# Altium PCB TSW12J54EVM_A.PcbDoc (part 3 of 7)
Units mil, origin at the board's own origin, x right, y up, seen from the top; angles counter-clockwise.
Board outline 6301 x 2680 mil, 10 copper layers (Top Layer - L1, Gnd-Plane - L2, Signals - L3, Gnd-Plane - L4, Pwr Plane - L5, Signals - L6, Gnd-Plane - L7, Signals - L8, Gnd-Plane - L9, Bottom Layer - L10), stack 57.8 mil thick; 650 components, 374 nets, 2074 pads, 1402 vias.
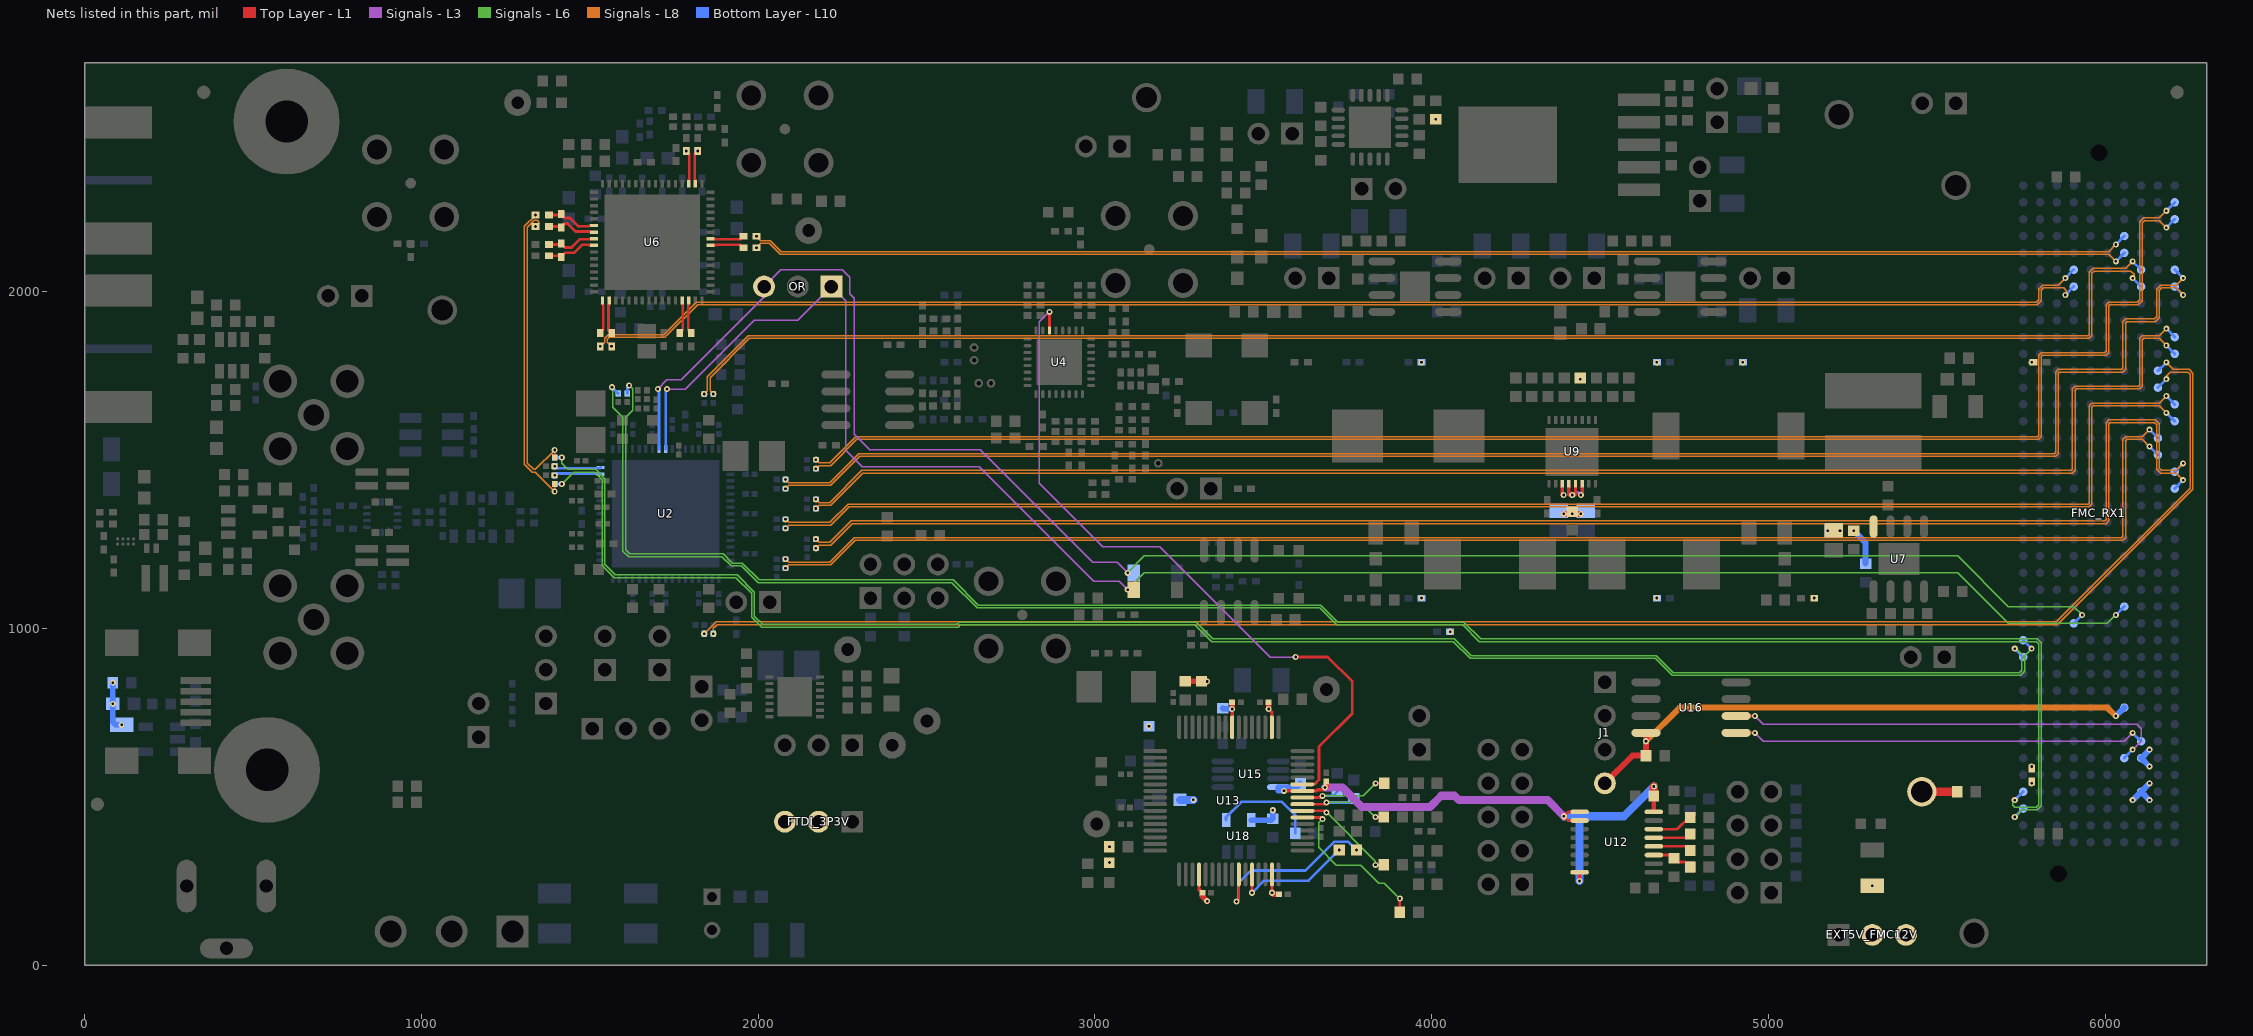
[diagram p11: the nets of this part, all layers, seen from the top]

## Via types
v1: diameter 18, hole 8, Top Layer - L1 to Bottom Layer - L10, tented both sides, 1120 vias
v2: diameter 19.68, hole 7.87, Top Layer - L1 to Bottom Layer - L10, 99 vias
v3: diameter 18, hole 8, Top Layer - L1 to Bottom Layer - L10, tented bottom, 42 vias
v4: diameter 18, hole 8, Top Layer - L1 to Bottom Layer - L10, tented top, 36 vias
v5: diameter 25, hole 10, Top Layer - L1 to Bottom Layer - L10, tented both sides, 32 vias
v6: diameter 21.46, hole 10, Top Layer - L1 to Bottom Layer - L10, tented both sides, 26 vias
v7: diameter 18, hole 8.01, Top Layer - L1 to Bottom Layer - L10, tented both sides, 16 vias
v8: diameter 18, hole 8.01, Top Layer - L1 to Bottom Layer - L10, tented bottom, 16 vias
v9: diameter 25.98, hole 12.99, Top Layer - L1 to Bottom Layer - L10, tented top, 8 vias
v10: diameter 19.68, hole 7.87, Top Layer - L1 to Bottom Layer - L10, tented top, 5 vias
v11: diameter 126, hole 106, Top Layer - L1 to Bottom Layer - L10, tented top, 2 vias

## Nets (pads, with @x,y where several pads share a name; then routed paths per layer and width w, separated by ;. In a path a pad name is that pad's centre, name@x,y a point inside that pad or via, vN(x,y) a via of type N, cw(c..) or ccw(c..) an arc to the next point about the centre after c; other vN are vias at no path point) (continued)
3P3V_FTDI: C118.1 C119.1 C129.1 C131.1 C132.1 C205.1 C213.1 C214.1 FTDI_3P3V.2 L24.1 L25.1 R66.2 R105.2 R106.2 R107.2 U12.1 U12.2 U12.8 U12.16 U13.20 U13.31 U13.42 U13.50 U13.56 U15.8 U18.5 USB_PWR.1 | length 2260.4
  Top Layer - L1 w8: U12.2@4438.76,429.5 4404.79,429.5 v1(4392,442.3) 4404.8,455.1 U12.1@4438.76,455.1
  Top Layer - L1 w10: U13.20@3308.89,269.5 3308.89,224.87 C118.1@3318.73,215.03 ; U13.56@3407.31,706.5 v1(3407.31,760.97) ; v1(3515.58,760.97) 3525.42,751.13 U13.50@3525.42,706.5 ; v1(3525.43,215.03) U13.31@3525.42,269.5 ; v1(3561.51,517.53) U13.42@3615.98,517.53 3658.83,517.53 3662.14,520.84 3676.47,520.84 v1(3683,527.37)
  Top Layer - L1 w13: v1(4438.76,250) U12.8@4438.76,275.96 ; U12.16@4659.24,455.1 C129.1@4659.24,502.06
  Top Layer - L1 w16: v1(3683,527.37) 3686.44,530.82 C131.1@3686.44,545.43
  Top Layer - L1 w16.5: R107.2@3268.2,842.56 v1(3333,842.56) ; C118.1@3318.73,215.03 3318.73,204.27 v1(3333,190) ; v1(3407.31,760.97) C132.1@3407.31,781.24 ; v1(3515.58,760.97) C214.1@3515.58,781.24 ; v1(3525.43,215.03) 3530.43,210.03 C119.1@3546.48,210.03
  Top Layer - L1 w24: C129.1@4659.24,502.06 v1(4659.24,530.79)
  Signals - L3 w24: v1(3683,527.37) 3734.63,527.37 3792,470 3995,470 4028,503 4068,503 4081,490 4344.3,490 v1(4392,442.3)
  Bottom Layer - L10 w16.5: R105.2@3379.32,762.56 3380.91,760.97 v1(3407.31,760.97) ; U18.5@3464.07,430.85 3523.59,430.85 C213.1@3528,435.25 v1(3528,460) ; v1(3561.51,517.53) 3544.68,517.53 U15.8@3544.68,528.61 3599.17,528.61 C205.1@3610,539.44
  Bottom Layer - L10 w24: L24.1@3252.5,491 v1(3292,491) ; v1(4392,442.3) 4438.76,442.3 ; v1(4438.76,250) 4438.76,442.3 ; v1(4659.24,530.79) 4570.75,442.3 4438.76,442.3
  other v1: 3042.91,304.73 3042.91,351.73 3160.56,709.56
3P3V_RX: 3P3RX.1 R132.1 | length 105.4
  Top Layer - L1 w25: 3P3RX.1@5455,515 R132.1@5560.44,515
3P3V_USB: C138.1 C210.1 FTDI_3P3V.3 L26.2 | length 146.8
  Bottom Layer - L10 w16.5: v1(83.74,839) 83.74,722.26 92.46,713.54 v1(110.24,713.54)
  other v1: 83.74,775.86
3P3VAUX: C143.1 FMC_RX1.D32 J1.4 U16.8 | length 1706.1
  Top Layer - L1 w18: J1.4@4514,540 4596,622 C143.1@4636.14,622 U16.8@4636.14,690
  Signals - L8 w18: v1(4636.14,665) 4736.14,765 6006,765 v3(6031,740)
  Bottom Layer - L10 w18: v3(6031,740) FMC_RX1.D32@6056,765
5P0_12P0V_INT: C94.1 C145.1 C146.1 C147.1 C167.1 C173.1 C184.1 C220.2 C221.2 C222.2 C223.2 C225.2 C226.2 C227.2 C261.1 EXT5V_FMC12V.2 R70.1 R78.1 R79.2 R94.2 U7.8 U9.11 U9.12 U9.13 U9.14 | length 307.8
  Top Layer - L1 w10: v1@4387.47,1396 U9.11@4387.47,1429.51 ; 4407.16,1396 U9.12@4407.16,1429.51 ; 4426.84,1396 U9.13@4426.84,1429.51 ; v1@4446.53,1396 U9.14@4446.53,1429.51
  Top Layer - L1 w18: v1(4391.47,1340) v1(4442.53,1340)
  Bottom Layer - L10 w8: 4434.77,1403.76 v1(4442.53,1396)
  Bottom Layer - L10 w18: v1@5253,1289.56 5288.19,1254.37 R70.1@5288.19,1192.41
  other v1: 5308,235.85 5781,590 4054.69,990 3969.69,1090 4668.31,1090 5135.69,1090 5176,1290 5212,1290 5253,1290 4417,1340 4391.47,1396 4417,1396 4441,1740 3969.69,1790 4668.31,1790 4923.69,1790 5781,1790 4011.68,2511.44
12P0V_RX: C94.2 EXT5V_FMC12V.3 FMC_RX1.C35 FMC_RX1.C37 | length 176.8
  Bottom Layer - L10 w18: v1(6081,490) FMC_RX1.C37@6106,515 ; v3(6131,490) FMC_RX1.C37@6106,515 ; v3(6131,540) FMC_RX1.C37@6106,515 ; v3(6131,590) FMC_RX1.C35@6106,615 v3(6131,640)
  other v1: 5781,540
ADC_OR_T0: D2.2 FMC_RX1.G27 OR.3 U2.25 | length 5339.6
  Signals - L3 w4: v1(1702.04,1710.8) 1729.24,1738 1771,1738 2017.5,1984.5 OR.3@2017.5,2015 2067.5,2065 2250,2065 2272,2043 2272,1993 2285,1980 2285,1577 2332,1530 2659,1530 2993,1196 3066,1196 v1(3097,1165)
  Signals - L6 w4: v1(3097,1165) 3147,1215 5561,1215 5711,1065 5906,1065 v3(5931,1040)
  Bottom Layer - L10 w8: v1(1702.04,1710.8) 1705.7,1707.14 U2.25@1705.7,1532.91 ; FMC_RX1.G27@5906,1015 v3(5931,1040)
ADC_OR_T1: D4.2 FMC_RX1.D26 OR.1 U2.26 | length 5368.5
  Signals - L3 w4: v1(1729.05,1710.8) 1783.8,1710.8 1988,1915 2117.5,1915 OR.1@2217.5,2015 2260,1972.5 2260,1529 2309,1480 2656,1480 2996,1140 3072,1140 v1(3097,1115)
  Signals - L6 w4: v1(3097,1115) 3147,1165 5561,1165 5711,1015 6006,1015 v3(6031,1040)
  Bottom Layer - L10 w8: U2.26@1725.39,1532.91 1725.39,1707.14 v1(1729.05,1710.8) ; v3(6031,1040) FMC_RX1.D26@6056,1065
CLK0_N: R63.1 U6.2 | length 101.6
  Top Layer - L1 w8: U6.2@1557.61,1973.77 1557.61,1961.77 1555.76,1959.93 1555.76,1885.68 R63.1@1564.76,1876.68
CLK0_P: R64.1 U6.1 | length 101.6
  Top Layer - L1 w8: R64.1@1530.76,1876.68 1539.76,1885.68 1539.76,1959.93 1537.92,1961.77 U6.1@1537.92,1973.77
CLK3_N: R61.1 U6.14 | length 101.6
  Top Layer - L1 w8: U6.14@1793.83,1973.77 1793.83,1961.77 1791.99,1959.93 1791.99,1885.68 R61.1@1800.98,1876.69
CLK3_P: R62.1 U6.13 | length 101.6
  Top Layer - L1 w8: R62.1@1766.98,1876.69 1775.98,1885.68 1775.98,1959.93 1774.14,1961.77 U6.13@1774.14,1973.77
CLK4_N: R59.1 U6.25 | length 101.6
  Top Layer - L1 w8: U6.25@1858.79,2156.84 1870.79,2156.84 1872.63,2155 1946.87,2155 R59.1@1955.87,2164
CLK4_P: R60.1 U6.24 | length 101.6
  Top Layer - L1 w8: U6.24@1858.79,2137.16 1870.79,2137.16 1872.63,2139 1946.87,2139 R60.1@1955.87,2130
CLK10_N: R160.1 R167.2 U6.55 | length 150.5
  Top Layer - L1 w8: R160.1@1378.47,2193.37 1412.56,2193.37 R167.2@1415.24,2190.68 1426.93,2202.37 1434.05,2202.37 1458.05,2178.37 1498.49,2178.37 1500.33,2176.53 U6.55@1512.33,2176.53
CLK10_P: R161.1 R167.1 U6.54 | length 150.5
  Top Layer - L1 w8: R161.1@1378.47,2227.37 1412.56,2227.37 R167.1@1415.24,2230.05 1426.93,2218.37 1440.68,2218.37 1464.68,2194.37 1498.49,2194.37 1500.33,2196.21 U6.54@1512.33,2196.21
CLK11_N: R43.1 R166.2 U6.57 | length 150.5
  Top Layer - L1 w8: R43.1@1378.47,2106 1412.56,2106 R166.2@1415.24,2103.31 1426.93,2115 1452.68,2115 1476.68,2139 1498.49,2139 1500.33,2137.16 U6.57@1512.33,2137.16
CLK11_P: R44.1 R166.1 U6.56 | length 150.5
  Top Layer - L1 w8: R44.1@1378.47,2140 1412.56,2140 R166.1@1415.24,2142.68 1426.93,2131 1446.05,2131 1470.05,2155 1498.49,2155 1500.33,2156.84 U6.56@1512.33,2156.84
CLKIN1_N: C112.1 C123.1 U6.35 | length 101.6
  Top Layer - L1 w8: v4(1786.67,2417.32) 1795.67,2408.32 1795.67,2334.07 1793.83,2332.23 U6.35@1793.83,2320.23
CLKIN1_P: C113.1 C114.2 U6.34 | length 101.6
  Top Layer - L1 w8: U6.34@1813.51,2320.23 1813.51,2332.23 1811.67,2334.07 1811.67,2408.32 v4(1820.67,2417.32)
D0_N: C9.1 FMC_RX1.C6 | length 4573.1
  Signals - L8 w4: v7(1839.84,1695.8) 1849.34,1705.3 1849.34,1747.83 1970.5,1869 5948.69,1869 5952,1872.31 5952,2057.31 5963.69,2069 6060,2069 v8(6081,2090)
  Bottom Layer - L10 w8: v8(6081,2090) FMC_RX1.C6@6106,2065
D0_P: C7.1 FMC_RX1.C7 | length 4573.3
  Signals - L8 w4: v7(1866.84,1695.8) 1857.34,1705.3 1857.34,1744.52 1973.82,1861 5952,1861 5960,1869 5960,2054 5967,2061 6076,2061 6086,2051 6086,2045 v8(6081,2040)
  Bottom Layer - L10 w8: v8(6081,2040) FMC_RX1.C7@6106,2015
D1_N: C12.1 FMC_RX1.A2 | length 4715.6
  Signals - L8 w4: v7(2171.19,1501.14) 2180.69,1491.64 2212.31,1491.64 2289.68,1569 5798.69,1569 5802,1572.31 5802,1811 5810,1819 5998.69,1819 6002,1822.31 6002,1961 6010,1969 6095,1969 6102,1976 6102,2207.31 6113.69,2219 6160,2219 v8(6181,2240)
  Bottom Layer - L10 w8: v8(6181,2240) FMC_RX1.A2@6206,2265
D1_P: C10.1 FMC_RX1.A3 | length 4715.6
  Signals - L8 w4: v7(2171.19,1474.14) 2180.69,1483.64 2215.63,1483.64 2292.99,1561 5802,1561 5810,1569 5810,1807.69 5813.31,1811 6002,1811 6010,1819 6010,1957.69 6013.31,1961 6098.31,1961 6110,1972.69 6110,2204 6117,2211 6160,2211 v8(6181,2190)
  Bottom Layer - L10 w8: v8(6181,2190) FMC_RX1.A3@6206,2215
D2_N: C14.1 FMC_RX1.A6 | length 4709.4
  Signals - L8 w4: v7(2081.19,1442.08) 2090.69,1432.58 2212.31,1432.58 2298.73,1519 5848.69,1519 5852,1522.31 5852,1761 5860,1769 6048.69,1769 6052,1772.31 6052,1911 6060,1919 6145,1919 6152,1926 6152,2007.31 6163.69,2019 6210,2019 v8(6231,2040)
  Bottom Layer - L10 w8: FMC_RX1.A6@6206,2065 v8(6231,2040)
D2_P: C13.1 FMC_RX1.A7 | length 4709.4
  Signals - L8 w4: v7(2081.19,1415.08) 2090.69,1424.58 2215.63,1424.58 2302.05,1511 5852,1511 5860,1519 5860,1757.69 5863.31,1761 6052,1761 6060,1769 6060,1907.69 6063.31,1911 6148.31,1911 6160,1922.69 6160,2004 6167,2011 6210,2011 v8(6231,1990)
  Bottom Layer - L10 w8: FMC_RX1.A7@6206,2015 v8(6231,1990)
D3_N: C17.1 FMC_RX1.A10 | length 4484.1
  Signals - L8 w4: v7(2171.19,1383.03) 2180.69,1373.53 2212.31,1373.53 2307.79,1469 5898.69,1469 5902,1472.31 5902,1711 5910,1719 6098.69,1719 6102,1722.31 6102,1861 6110,1869 6160,1869 v8(6181,1890)
  Bottom Layer - L10 w8: v8(6181,1890) FMC_RX1.A10@6206,1865
D3_P: C15.1 FMC_RX1.A11 | length 4484.1
  Signals - L8 w4: v7(2171.19,1356.03) 2180.69,1365.53 2215.63,1365.53 2311.1,1461 5902,1461 5910,1469 5910,1707.69 5913.31,1711 6102,1711 6110,1719 6110,1857.69 6113.31,1861 6160,1861 v8(6181,1840)
  Bottom Layer - L10 w8: v8(6181,1840) FMC_RX1.A11@6206,1815
D4_N: C21.1 FMC_RX1.A14 | length 4463.8
  Signals - L8 w4: v7(2081.19,1323.97) 2090.69,1314.47 2212.31,1314.47 2266.84,1369 5948.69,1369 5952,1372.31 5952,1661 5960,1669 6160,1669 v8(6181,1690)
  Bottom Layer - L10 w8: v8(6181,1690) FMC_RX1.A14@6206,1665
D4_P: C20.1 FMC_RX1.A15 | length 4463.8
  Signals - L8 w4: v7(2081.19,1296.97) 2090.69,1306.47 2215.63,1306.47 2270.16,1361 5952,1361 5960,1369 5960,1657.69 5963.31,1661 6160,1661 v8(6181,1640)
  Bottom Layer - L10 w8: v8(6181,1640) FMC_RX1.A15@6206,1615
D5_N: C23.1 FMC_RX1.A18 | length 4566.6
  Signals - L8 w4: v7(2171.19,1264.92) 2180.69,1255.42 2212.31,1255.42 2275.9,1319 5998.69,1319 6002,1322.31 6002,1611 6010,1619 6148.31,1619 6160,1607.31 6160,1476 6167,1469 6210,1469 v8(6231,1490)
  Bottom Layer - L10 w8: FMC_RX1.A18@6206,1465 v8(6231,1490)
D5_P: C22.1 FMC_RX1.A19 | length 4566.6
  Signals - L8 w4: v7(2171.19,1237.92) 2180.69,1247.42 2215.63,1247.42 2279.21,1311 6002,1311 6010,1319 6010,1607.69 6013.31,1611 6145,1611 6152,1604 6152,1472.69 6163.69,1461 6210,1461 v8(6231,1440)
  Bottom Layer - L10 w8: FMC_RX1.A19@6206,1415 v8(6231,1440)
D6_N: C28.1 FMC_RX1.B16 | length 4421.3
  Signals - L8 w4: v7(2081.19,1205.86) 2090.69,1196.36 2212.31,1196.36 2284.95,1269 6048.69,1269 6052,1272.31 6052,1561 6060,1569 6110,1569 v8(6131,1590)
  Bottom Layer - L10 w8: v8(6131,1590) FMC_RX1.B16@6156,1565
D6_P: C26.1 FMC_RX1.B17 | length 4421.3
  Signals - L8 w4: v7(2081.19,1178.86) 2090.69,1188.36 2215.63,1188.36 2288.27,1261 6052,1261 6060,1269 6060,1557.69 6063.31,1561 6110,1561 v8(6131,1540)
  Bottom Layer - L10 w8: v8(6131,1540) FMC_RX1.B17@6156,1515
D7_N: C31.1 FMC_RX1.B12 | length 5052
  Signals - L8 w4: v7(1866.84,984.2) 1866.84,999.89 1878.15,1011.2 5857.86,1011.2 6260,1413.34 6260,1757.31 6248.31,1769 6202,1769 v8(6181,1790)
  Bottom Layer - L10 w8: FMC_RX1.B12@6156,1765 v8(6181,1790)
D7_P: C29.1 FMC_RX1.B13 | length 5051.9
  Signals - L8 w4: v7(1839.84,984.2) 1874.84,1019.2 5854.54,1019.2 6252,1416.66 6252,1754 6245,1761 6193,1761 6181,1749 v8(6181,1740)
  Bottom Layer - L10 w8: FMC_RX1.B13@6156,1715 v8(6181,1740)
DEV_CLK_N: C263.2 R160.2 | length 898.6
  Top Layer - L1 w4: C263.2@1395.57,1507.44 v1(1395.57,1529.49)
  Signals - L8 w4: v1(1339.1,2193.37) 1348.22,2202.49 1348.22,2208 1343.86,2212.37 1335.41,2212.37 1314,2190.96 1314,1491.01 1333.06,1471.95 1338.03,1471.95 v1(1395.57,1529.49)
DEV_CLK_P: C262.2 R161.2 | length 898.7
  Top Layer - L1 w8: v1(1395.57,1406.41) C262.2@1395.57,1428.47
  Signals - L8 w4: v1(1339.1,2227.37) 1306,2194.27 1306,1487.7 1329.75,1463.95 1338.03,1463.95 v1(1395.57,1406.41)
DEVCLK_N: C33.1 C36.1 C93.1 C263.1 U2.16 | length 139.9
  Bottom Layer - L10 w8: v1(1395.57,1481.45) 1401.07,1475.95 1530.63,1475.95 U2.16@1532.47,1477.8
DEVCLK_P: C30.1 C32.1 C92.1 C262.1 U2.15 | length 139.9
  Bottom Layer - L10 w8: v1(1395.57,1454.45) 1401.07,1459.95 1530.63,1459.95 U2.15@1532.47,1458.11
DEVCLKARX_N: FMC_RX1.D5 R60.2 | length 4098.5
  Signals - L8 w4: v1(1995.24,2130) 2008.25,2143 2033.06,2143 2065.06,2111 6010,2111 v3(6031,2090)
  Bottom Layer - L10 w8: v3(6031,2090) FMC_RX1.D5@6056,2115
DEVCLKARX_P: FMC_RX1.D4 R59.2 | length 4098.4
  Signals - L8 w4: v1(1995.25,2164) 2008.24,2151 2036.37,2151 2068.38,2119 6010,2119 v3(6031,2140)
  Bottom Layer - L10 w8: v3(6031,2140) FMC_RX1.D4@6056,2165
DEVCLKBRX_N: FMC_RX1.G7 R63.2 | length 4494.7
  Signals - L8 w4: v1(1564.76,1837.31) 1551.76,1850.32 1551.76,1858.13 1557.95,1864.32 1723.32,1864.32 1820,1961 5798.31,1961 5810,1972.69 5810,2004 5817,2011 5876,2011 5886,2001 5886,1995 v3(5881,1990)
  Bottom Layer - L10 w8: v3(5881,1990) FMC_RX1.G7@5906,2015
DEVCLKBRX_P: FMC_RX1.G6 R64.2 | length 4494.4
  Signals - L8 w4: v1(1530.76,1837.32) 1543.76,1850.32 1543.76,1861.45 1554.63,1872.32 1720,1872.32 1816.69,1969 5795,1969 5802,1976 5802,2007.31 5813.69,2019 5860,2019 v3(5881,2040)
  Bottom Layer - L10 w8: v3(5881,2040) FMC_RX1.G6@5906,2065
EE_ADDR0_RX: FMC_RX1.C34 U16.1 | length 1233.2
  Top Layer - L1 w8: U16.1@4903.86,690 v1(4959.16,690)
  Signals - L3 w4: v1(4959.16,690) 4984.16,665 6056,665 v3(6081,690)
  Bottom Layer - L10 w8: v3(6081,690) FMC_RX1.C34@6106,665
EE_ADDR1_RX: FMC_RX1.D35 U16.2 | length 1325.6
  Top Layer - L1 w8: U16.2@4903.86,740 v1(4959.16,740)
  Signals - L3 w4: v1(4959.16,740) 4984.17,715 6093,715 6106,702 6106,665 v3(6081,640)
  Bottom Layer - L10 w8: FMC_RX1.D35@6056,615 v3(6081,640)
FMC_DEVCLK_N: C93.2 FMC_RX1.K29 | length 4941.1
  Signals - L6 w4: v1(1416.84,1507.44) 1416.84,1489.67 1434.56,1471.95 1517.63,1471.95 1545.08,1444.5 1545.08,1190.03 1576.11,1159 1937.31,1159 1989,1107.31 1989,1036.2 2013.2,1012 2589.99,1012 2596.99,1019 3300,1019 3350,969 4067,969 4117,919 4667,919 4717,869 5745,869 5752,876 5752,923 5735,940 v3(5731,940)
  Bottom Layer - L10 w8: C93.2@1395.57,1507.44 v1(1416.84,1507.44) ; v3(5731,940) FMC_RX1.K29@5756,915
FMC_DEVCLK_P: C92.2 FMC_RX1.K28 | length 4941.6
  Signals - L6 w4: v1(1416.84,1428.47) 1452.32,1463.95 1514.31,1463.95 1537.08,1441.18 1537.08,1186.71 1572.8,1151 1934,1151 1981,1104 1981,1032.89 2009.89,1004 2593.3,1004 2600.3,1011 3296.69,1011 3346.69,961 4063.69,961 4113.69,911 4663.69,911 4713.69,861 5748.31,861 5760,872.69 5760,919 v3(5781,940)
  Bottom Layer - L10 w8: C92.2@1395.57,1428.47 v1(1416.84,1428.47) ; FMC_RX1.K28@5756,965 v3(5781,940)
FMC_SYSREF_N: C91.2 FMC_RX1.K38 | length 5456.4
  Signals - L6 w4: v1(1616.96,1720.97) 1626.96,1710.97 1626.96,1647 1606.35,1626.39 1606.35,1233.09 1618.47,1220.97 1895.83,1220.97 1922.63,1194.16 1953.25,1194.16 2003.42,1144 2578.62,1144 2653.61,1069 3671,1069 3721,1019 4095,1019 4145,969 5798.31,969 5810,957.31 5810,472.69 5798.31,461 5752,461 v3(5731,440)
  Bottom Layer - L10 w8: C91.2@1610.93,1697.99 1610.93,1714.94 v1(1616.96,1720.97) ; v3(5731,440) FMC_RX1.K38@5756,465
FMC_SYSREF_P: C90.2 FMC_RX1.K37 | length 5456.2
  Signals - L6 w4: v1(1565.93,1715.99) 1567.91,1714.02 1567.91,1656.84 1598.35,1626.39 1598.35,1229.77 1615.16,1212.97 1892.51,1212.97 1919.32,1186.16 1949.94,1186.16 2000.1,1136 2575.3,1136 2650.3,1061 3667.69,1061 3717.69,1011 4091.69,1011 4141.69,961 5795,961 5802,954 5802,476 5795,469 5731,469 5725,475 5725,484 v3(5731,490)
  Bottom Layer - L10 w8: v1(1565.93,1715.99) C90.2@1583.93,1697.99 ; v3(5731,490) FMC_RX1.K37@5756,515
FTDI_ADC_SCLK: R109.2 U12.14 | length 122.5
  Top Layer - L1 w8: U12.14@4659.24,403.91 4728.85,403.91 4763.44,438.5 R109.2@4767.44,438.5
FTDI_ADC_SCSB: R118.2 R123.1 U12.11 | length 123
  Top Layer - L1 w8: U12.11@4659.24,327.14 4709.94,327.14 R123.1@4719,318.09 4730.56,306.53 4752.41,306.53 R118.2@4767.44,291.5
FTDI_ADC_SDI: R111.2 U12.13 | length 112.8
  Top Layer - L1 w8: U12.13@4659.24,378.32 4756.26,378.32 R111.2@4767.44,389.5
FTDI_ADC_SDO: R110.2 U12.12 | length 113.3
  Top Layer - L1 w8: U12.12@4659.24,352.73 4755.21,352.73 R110.2@4767.44,340.5
FTDI_LMK_CSB: R68.2 R130.2 U13.40 | length 347.3
  Top Layer - L1 w8: U13.40@3615.98,478.16 3682.45,478.16 v1(3687.44,483.16) ; v1(3832.88,440) R68.2@3857.88,440
  Signals - L6 w4: v1(3687.44,483.16) 3789.72,483.16 v1(3832.88,440)
  Bottom Layer - L10 w8: v1(3687.44,483.16) 3756.25,483.16 R130.2@3768,494.9
FTDI_LMK_TRF_CLK: R115.2 U13.38 | length 494.8
  Top Layer - L1 w8: U13.38@3615.98,438.79 3670.45,438.79 v1(3675.44,433.79) ; R115.2@3905.32,157.56 v1(3905.32,198)
  Signals - L6 w4: v1(3675.44,433.79) 3664,422.34 3664,350 3717,297 3789,297 3842,244 3859.32,244 v1(3905.32,198)
FTDI_LMK_TRF_DATA: R114.2 U13.39 | length 314.3
  Top Layer - L1 w8: U13.39@3615.98,458.47 3682.45,458.47 v1(3687.44,453.47) ; v1(3832.88,298) R114.2@3857.88,298
  Signals - L6 w4: v1(3687.44,453.47) 3832.88,308.04 v1(3832.88,298)
FTDI_TRF_R1: U4.6 U13.43 | length 2136.4
  Top Layer - L1 w8: U4.6@2864.71,1884.49 v1(2864.71,1940) ; v1(3596,915) 3691,915 3764,842 3764,748 3665,649 3665,551 3651.21,537.21 U13.43@3615.98,537.21
  Signals - L3 w4: v1(2864.71,1940) 2835.18,1910.47 2835.18,1430.82 3023,1243 3193,1243 3521,915 v1(3596,915)
FTDI_TRF_STROBE: R113.2 R131.2 U13.41 | length 308.3
  Top Layer - L1 w8: U13.41@3615.98,497.84 3670.45,497.84 v1(3675.44,502.84) ; v1(3833.44,540) R113.2@3858.44,540
  Signals - L6 w4: v1(3675.44,502.84) 3796.28,502.84 v1(3833.44,540)
  Bottom Layer - L10 w8: v1(3675.44,502.84) 3707.25,502.84 R131.2@3719,514.59
FTDI_TS_SMBCLK: R125.2 U13.26 | length 552.5
  Top Layer - L1 w8: v1(3420,189.03) 3427,196.03 U13.26@3427,269.5
  Bottom Layer - L10 w8: v1(3420,189.03) 3427,196.03 3427,245 3463,281 3625,281 3710.77,366.77 3751.8,366.77 v1(3776.56,342.01)
FTDI_TS_SMBDAT_IN: R124.2 U13.28 | length 365.7
  Top Layer - L1 w8: v1(3466.37,215.03) U13.28@3466.37,269.5
  Bottom Layer - L10 w8: v1(3466.37,215.03) 3502.34,251 3633.99,251 v1(3725,342.01)
FTDI_TS_SMBDAT_OUT: R117.2 U18.4 | length 302.4
  Bottom Layer - L10 w8: U18.4@3389.29,430.85 3389.29,439.29 3435,485 3555,485 3594.7,445.3 R117.2@3594.7,392.13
